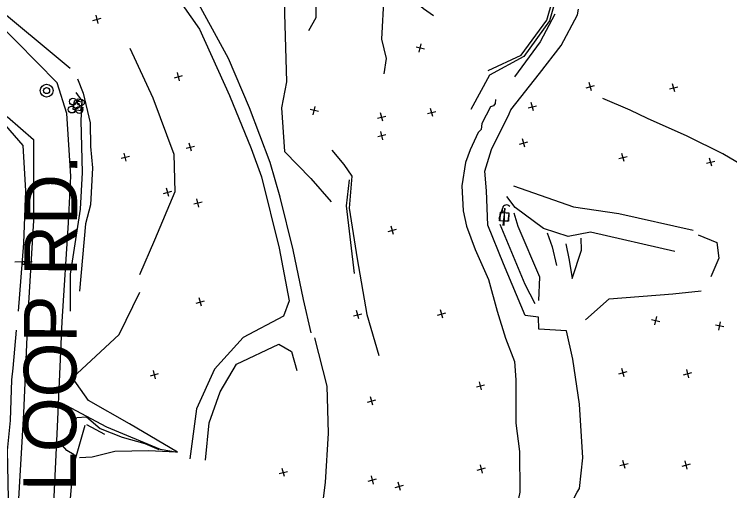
# Model space of a CAD drawing. Extents: x 4711259 to 4716401, y 890074 to 892728.
# Drawn here: x 4712586.5 to 4713004.8, y 891673.4 to 891952.1 of the extents above; entities that cross this region are included whole.
import ezdxf

# ---------------------------------------------------------------- set-up
doc = ezdxf.new("R2010")
doc.units = 0
for name, color, linetype in [('E_HY_STORM_MH', 7, 'Continuous'), ('E_RDWY_ROAD_Bollard', 7, 'Continuous'), ('E_RDWY_ROAD_EdgeAsph', 7, 'Continuous'), ('E_RDWY_ROAD_EdgeConc', 7, 'Continuous'), ('E_RDWY_ROAD_EdgeGravel', 7, 'Continuous'), ('E_RDWY_ROAD_NameTx', 7, 'Continuous'), ('E_TERR_DTM_BrkLines', 7, 'Continuous'), ('E_TERR_DTM_RandomPt', 7, 'Continuous'), ('E_TRAF_SIGN_PrivateSign', 7, 'Continuous'), ('E_UTIL_ELEC_POLE', 7, 'Continuous'), ('E_UTIL_WTR_General', 7, 'Continuous')]:
    doc.layers.add(name, color=color, linetype=linetype)

msp = doc.modelspace()

# ---------------------------------------------------------------- linework, layer by layer
at = {"layer": 'E_HY_STORM_MH'}
for radius in [3.75, 1.76]:
    msp.add_circle((4712605.35, 891907.48), radius, dxfattribs=at)
at = {"layer": 'E_RDWY_ROAD_Bollard'}
for centre in [(4712620.77, 891901.05), (4712625.41, 891900.53), (4712620.03, 891896.42), (4712624.48, 891896.16)]:
    msp.add_circle(centre, 2, dxfattribs=at)
at = {"layer": 'E_RDWY_ROAD_EdgeAsph'}
for points in [[(4712760.1, 891765.66), (4712755.63, 891785.3), (4712749.62, 891814.3), (4712741.98, 891845.07), (4712736.16, 891865.38), (4712724.05, 891897.35), (4712711.66, 891926.28), (4712689.64, 891966.85), (4712669.47, 891991.05), (4712652.59, 892010.23)], [(4712646.76, 892004.97), (4712672.14, 891975.74), (4712694.78, 891943.37), (4712712.35, 891904.69), (4712724.92, 891873.55), (4712730.93, 891857.01), (4712741.35, 891815.24), (4712747.28, 891784.56), (4712743.86, 891775.44), (4712720.4, 891763.01), (4712703.46, 891744.46), (4712692.95, 891721.19), (4712689.17, 891692.09)], [(4712862.6, 891848.83), (4712861.7, 891860.44), (4712865.6, 891872.96), (4712875.86, 891893.98), (4712876.77, 891896.22), (4712893.53, 891917.55), (4712906.3, 891933.9), (4712915.74, 891951.85), (4712916.41, 891955.05)], [(4712735.9, 891562.86), (4712714.82, 891528.34), (4712688.44, 891495.14), (4712667.15, 891473.19), (4712649.72, 891460.53), (4712632.13, 891450.87), (4712610.67, 891440.52), (4712601.83, 891443.5), (4712598.88, 891448.47), (4712599.81, 891485.64), (4712601.62, 891522.38), (4712604.11, 891565.54), (4712606.51, 891615.64), (4712609.62, 891665.6), (4712611.64, 891710.78), (4712614.55, 891772.4), (4712618.2, 891830.11), (4712619.55, 891857.41), (4712617.18, 891894.05), (4712611.49, 891911.96), (4712575.66, 891948.29)], [(4712902.54, 891952.19), (4712894.01, 891936.04), (4712879.04, 891915.48)], [(4712867.8, 891902.23), (4712867.64, 891900.02), (4712866.69, 891898.64), (4712864.89, 891897.9), (4712859.83, 891888.25), (4712859.39, 891884.75), (4712857.78, 891883.04), (4712853.02, 891872.77), (4712850.33, 891865.5), (4712848.26, 891851.7), (4712848.87, 891837.17), (4712850.87, 891828.25), (4712855.99, 891814.5), (4712863.69, 891796.95), (4712868.89, 891778.41), (4712873.66, 891762.58)], [(4712304.96, 891896.85), (4712384.63, 891896.03), (4712434.12, 891895.34), (4712491.07, 891894.75), (4712543.41, 891894.49), (4712582.4, 891892.24), (4712597.63, 891878.83), (4712597.65, 891831.39), (4712594.45, 891776.63), (4712591.79, 891718.65), (4712588.49, 891662.05), (4712585.87, 891611.48), (4712584.5, 891595.88), (4712574.49, 891585.03), (4712562.61, 891582.71), (4712492.86, 891582.66), (4712437.1, 891583.09), (4712367.74, 891583.27), (4712291.22, 891584.33)], [(4712873.86, 891570.04), (4712879.32, 891584.58), (4712888.45, 891611.83), (4712895.03, 891627.76), (4712902.53, 891647.52), (4712915.63, 891672.52), (4712916.97, 891674.68), (4712918.89, 891692.61), (4712916.93, 891724.02), (4712913.1, 891750.3), (4712909.35, 891767), (4712893.28, 891767.97), (4712893.07, 891774.97), (4712885.3, 891775.81), (4712872.53, 891806.07), (4712863.37, 891828.76), (4712862.6, 891848.83)], [(4712762.03, 891762.78), (4712769.15, 891734.58), (4712770.05, 891707.05), (4712768.24, 891678.07), (4712764.23, 891645.84), (4712763.06, 891627.61), (4712761.25, 891608.18)], [(4712698.36, 891691.23), (4712700.34, 891713.08), (4712706.79, 891731.21), (4712716.31, 891747.43), (4712741.08, 891759.1), (4712748.53, 891754.81), (4712751.64, 891743.76)]]:
    msp.add_lwpolyline(points, dxfattribs=at)
at = {"layer": 'E_RDWY_ROAD_EdgeConc'}
msp.add_lwpolyline([(4712621.43, 891901.53), (4712620.66, 891896.61), (4712625.44, 891895.86), (4712626.21, 891900.78)], close=True, dxfattribs=at)
at = {"layer": 'E_RDWY_ROAD_EdgeGravel'}
for points in [[(4713021.65, 891858.22), (4713000.86, 891870.4), (4712979.89, 891880.86), (4712956.72, 891891.11), (4712946.64, 891895.97), (4712930.63, 891902.8)], [(4712621.38, 891694.39), (4712617.26, 891696.8), (4712613.31, 891701.32)], [(4712681.02, 891695.85), (4712665.11, 891696.62), (4712645.26, 891696.27), (4712632.09, 891693.07), (4712624.55, 891692.55)]]:
    msp.add_lwpolyline(points, dxfattribs=at)
at = {"layer": 'E_TERR_DTM_BrkLines'}
for points in [[(4712619.1, 891920.49), (4712572.27, 891959.19), (4712536.3, 891994.41), (4712505.02, 892028.08), (4712471.23, 892061.89), (4712434.73, 892100.76), (4712415.26, 892119.86), (4712399.71, 892137)], [(4712877.64, 892030.04), (4712915.02, 892029.31), (4712919.05, 892026.68), (4712920.64, 892020.37), (4712914.86, 892002.75), (4712899.48, 891948.35), (4712884.52, 891927.46), (4712864.28, 891916.6), (4712853.46, 891896.39)], [(4712863.67, 891919.34), (4712882.8, 891928.28), (4712897.94, 891948.71), (4712913.22, 892002.44), (4712917.82, 892021.28), (4712915.43, 892025.84), (4712877.75, 892027.35)], [(4712822.92, 892005.1), (4712821.63, 891998.89), (4712820.3, 891991.91), (4712817.78, 891984.26), (4712819.1, 891976.25), (4712815.51, 891964.79), (4712825.76, 891955.62), (4712831.54, 891951.53)], [(4712695.13, 891991.34), (4712735.8, 891984.81), (4712744.56, 891980.6), (4712744.56, 891952.59), (4712745.6, 891912.68), (4712742.75, 891897.49), (4712744.46, 891871.92), (4712759.96, 891856.15), (4712771.78, 891842.31)], [(4712767.39, 891977.09), (4712762.85, 891964.21), (4712762.74, 891950.08), (4712758.55, 891942.46)], [(4712802.59, 891963.2), (4712801.14, 891937.51), (4712803.88, 891926.3), (4712802.55, 891917.23)], [(4712654.09, 891932.29), (4712667.48, 891903.34), (4712679.85, 891870.31), (4712680.35, 891848.24), (4712668.5, 891820), (4712659.59, 891799.68)], [(4712623.39, 891914.33), (4712626.76, 891906.01), (4712630.81, 891888.6), (4712630.98, 891874.69), (4712632.17, 891862.29), (4712631.02, 891840.7), (4712628.14, 891829.53), (4712624.64, 891790.06)], [(4712619.41, 891778.43), (4712619.38, 891800.01), (4712625.11, 891838.05), (4712626.38, 891859.62), (4712625.66, 891889.98), (4712626.25, 891901.52), (4712622.64, 891906.45)], [(4712588.91, 891778.44), (4712592.04, 891818.18), (4712593.13, 891848.88), (4712591.62, 891875.44), (4712581.43, 891887.14), (4712533.27, 891889.67), (4712492.53, 891889.57), (4712481.34, 891887.18), (4712481.48, 891875.5)], [(4712772.19, 891872.59), (4712779.17, 891864.3), (4712783.79, 891857.46), (4712782.31, 891838.75), (4712787.04, 891809.09), (4712792.67, 891776.52), (4712799.56, 891752.49)], [(4712782.34, 891855.22), (4712780.54, 891840.01), (4712785.21, 891800.38)], [(4712878.3, 891851.72), (4712913.48, 891839.43), (4712939.91, 891835.66), (4712983.37, 891825.87)], [(4712972.71, 891813.26), (4712923.41, 891824.6), (4712910.44, 891822.11), (4712896, 891826.74), (4712879.29, 891839.03), (4712874.52, 891845.54)], [(4712893.2, 891784.65), (4712893.84, 891798.24), (4712881.11, 891827.88), (4712878.81, 891835.83)], [(4712870.47, 891829.37), (4712884.98, 891794.14), (4712890.89, 891782.82)], [(4712898.11, 891824.19), (4712901.01, 891815.98), (4712903.58, 891805.22)], [(4712986.29, 891823.02), (4712997.28, 891818.65), (4712998.44, 891809.36), (4712993.8, 891798.47)], [(4712908.94, 891817.87), (4712910.96, 891808.35), (4712912.77, 891797.47), (4712918.07, 891814.08), (4712917.93, 891821.17)], [(4712616.64, 891723.47), (4712640.47, 891710.75), (4712671.76, 891697.71), (4712681.81, 891695.87), (4712653.91, 891712.43), (4712629.81, 891726.17), (4712620.44, 891739.47), (4712647.82, 891764.77), (4712659.91, 891789.49)], [(4712920.42, 891773.27), (4712934.43, 891785.72), (4712971.61, 891788.5), (4712988.2, 891790.42)], [(4712587.58, 891767.34), (4712585.52, 891745.07), (4712584.8, 891738.29), (4712584.06, 891714.42), (4712582.23, 891696.91), (4712582.69, 891678.56), (4712583.02, 891658.08), (4712581.39, 891638.94), (4712580.64, 891623.52), (4712583.73, 891612.8)], [(4712873.66, 891762.58), (4712878.96, 891748.96), (4712879.73, 891738.18), (4712879.82, 891712.94), (4712881.94, 891696.31), (4712882.13, 891672.43), (4712878.58, 891655.99), (4712877.23, 891645.9), (4712873.94, 891637.19), (4712870.34, 891624.36)], [(4712618.01, 891701.7), (4712619.56, 891709.21), (4712623.12, 891716.2), (4712628.64, 891716.61), (4712636.68, 891709.81), (4712649.56, 891704.77), (4712662.83, 891701.06), (4712671.05, 891697.42)], [(4712620.89, 891463.57), (4712624.86, 891522.85), (4712630.79, 891580.47), (4712616.4, 891634.39), (4712620.83, 891687.19), (4712627.84, 891711.72)], [(4712639.4, 891706.3), (4712634.43, 891709.03), (4712628.89, 891711.99)]]:
    msp.add_lwpolyline(points, dxfattribs=at)
at = {"layer": 'E_TERR_DTM_RandomPt'}
for p, q in [((4712632.47, 891948.55), (4712637.3, 891949.82)), ((4712635.52, 891946.76), (4712634.25, 891951.6)), ((4712826.32, 891931.78), (4712821.45, 891932.91)), ((4712823.31, 891929.91), (4712824.45, 891934.78)), ((4712680.06, 891915.02), (4712684.89, 891916.29)), ((4712683.11, 891913.23), (4712681.84, 891918.07)), ((4712923.93, 891907.35), (4712922.66, 891912.19)), ((4712972.74, 891906.71), (4712971.47, 891911.55)), ((4712920.87, 891909.13), (4712925.71, 891910.4)), ((4712969.68, 891908.49), (4712974.52, 891909.76)), ((4712761.29, 891893.38), (4712762.42, 891898.25)), ((4712886.95, 891897.37), (4712891.78, 891898.67)), ((4712890.01, 891895.61), (4712888.72, 891900.44)), ((4712764.29, 891895.24), (4712759.42, 891896.38)), ((4712801.91, 891889.57), (4712800.64, 891894.41)), ((4712828.15, 891894.06), (4712832.99, 891895.33)), ((4712831.21, 891892.28), (4712829.94, 891897.11)), ((4712798.86, 891891.36), (4712803.69, 891892.63)), ((4712798.99, 891880.56), (4712803.82, 891881.83)), ((4712802.04, 891878.77), (4712800.77, 891883.61)), ((4712881.89, 891876.2), (4712886.72, 891877.47)), ((4712884.94, 891874.42), (4712883.67, 891879.26)), ((4712687.04, 891873.77), (4712691.88, 891875.04)), ((4712690.09, 891871.98), (4712688.82, 891876.82)), ((4712648.91, 891867.89), (4712653.74, 891869.16)), ((4712651.96, 891866.11), (4712650.69, 891870.94)), ((4712940.03, 891867.73), (4712944.87, 891869)), ((4712943.08, 891865.95), (4712941.81, 891870.78)), ((4712991.32, 891865), (4712996.16, 891866.27)), ((4712994.38, 891863.22), (4712993.11, 891868.05)), ((4712673.73, 891847.34), (4712678.57, 891848.61)), ((4712676.78, 891845.56), (4712675.51, 891850.4)), ((4712694.47, 891839.36), (4712693.2, 891844.19)), ((4712691.42, 891841.14), (4712696.25, 891842.41)), ((4712808.21, 891823.32), (4712806.94, 891828.16)), ((4712805.15, 891825.1), (4712809.99, 891826.37)), ((4712695.87, 891781.39), (4712694.6, 891786.22)), ((4712692.81, 891783.17), (4712697.65, 891784.44)), ((4712784.84, 891775.68), (4712789.68, 891776.95)), ((4712787.9, 891773.9), (4712786.63, 891778.74)), ((4712833.95, 891776.13), (4712838.79, 891777.4)), ((4712837, 891774.34), (4712835.73, 891779.18)), ((4712964.03, 891772.25), (4712959.16, 891773.38)), ((4712961.03, 891770.38), (4712962.17, 891775.25)), ((4713001.4, 891769.2), (4712996.53, 891770.33)), ((4712998.4, 891767.33), (4712999.53, 891772.2)), ((4712669.09, 891738.87), (4712667.82, 891743.71)), ((4712943.04, 891739.99), (4712941.77, 891744.82)), ((4712980.93, 891739.41), (4712979.66, 891744.24)), ((4712666.04, 891740.65), (4712670.88, 891741.92)), ((4712939.99, 891741.77), (4712944.82, 891743.04)), ((4712977.87, 891741.19), (4712982.71, 891742.46)), ((4712856.69, 891734.09), (4712861.53, 891735.36)), ((4712859.74, 891732.3), (4712858.47, 891737.14)), ((4712793.07, 891725.24), (4712797.9, 891726.51)), ((4712796.12, 891723.46), (4712794.85, 891728.29)), ((4712940.62, 891688.08), (4712945.46, 891689.35)), ((4712943.68, 891686.29), (4712942.4, 891691.13)), ((4712976.99, 891687.81), (4712981.82, 891689.08)), ((4712980.04, 891686.02), (4712978.77, 891690.86)), ((4712741.39, 891683.37), (4712746.23, 891684.64)), ((4712744.44, 891681.59), (4712743.17, 891686.43)), ((4712857.22, 891685.41), (4712862.06, 891686.68)), ((4712860.28, 891683.63), (4712859, 891688.47)), ((4712796.55, 891677.22), (4712795.28, 891682.06)), ((4712793.5, 891679), (4712798.33, 891680.28)), ((4712809.23, 891675.23), (4712814.06, 891676.52)), ((4712812.29, 891673.46), (4712810.99, 891678.29))]:
    msp.add_line(p, q, dxfattribs=at)
at = {"layer": 'E_TRAF_SIGN_PrivateSign'}
for p, q in [((4712586.87, 891807.29), (4712596.87, 891807.44)), ((4712591.88, 891806.61), (4712591.88, 891806.61))]:
    msp.add_line(p, q, dxfattribs=at)
msp.add_lwpolyline([(4712591.12, 891807.35), (4712591.15, 891805.85), (4712592.65, 891805.88), (4712592.62, 891807.37)], close=True, dxfattribs=at)
at = {"layer": 'E_UTIL_ELEC_POLE'}
for p, q in [((4712870.01, 891832.56), (4712872.59, 891839.93)), ((4712872.38, 891828.6), (4712873.53, 891838.53)), ((4712872.93, 891828.64), (4712873.36, 891838.63))]:
    msp.add_line(p, q, dxfattribs=at)
for points in [[(4712870.18, 891831.37), (4712870.76, 891836.34), (4712875.73, 891835.76), (4712875.15, 891830.8)], [(4712870.54, 891831.25), (4712870.76, 891836.24), (4712875.75, 891836.02), (4712875.53, 891831.03)]]:
    msp.add_lwpolyline(points, close=True, dxfattribs=at)
msp.add_arc((4712874.29, 891838.09), 2.5, 38.5115, 226.7401, dxfattribs=at)
at = {"layer": 'E_UTIL_WTR_General'}
for p, q in [((4712623.16, 891900.53), (4712623.75, 891902.96)), ((4712620.89, 891899.16), (4712618.46, 891899.76)), ((4712624.53, 891898.26), (4712626.95, 891897.66)), ((4712622.26, 891896.89), (4712621.66, 891894.46))]:
    msp.add_line(p, q, dxfattribs=at)
msp.add_circle((4712622.71, 891898.71), 1.87, dxfattribs=at)

# ---------------------------------------------------------------- texts
at = {"layer": 'E_RDWY_ROAD_NameTx'}
msp.add_text('LOOP RD.', height=30.84, rotation=89.7618, dxfattribs=at).set_placement((4712622.56, 891672.91))

doc.saveas('drawing.dxf')
